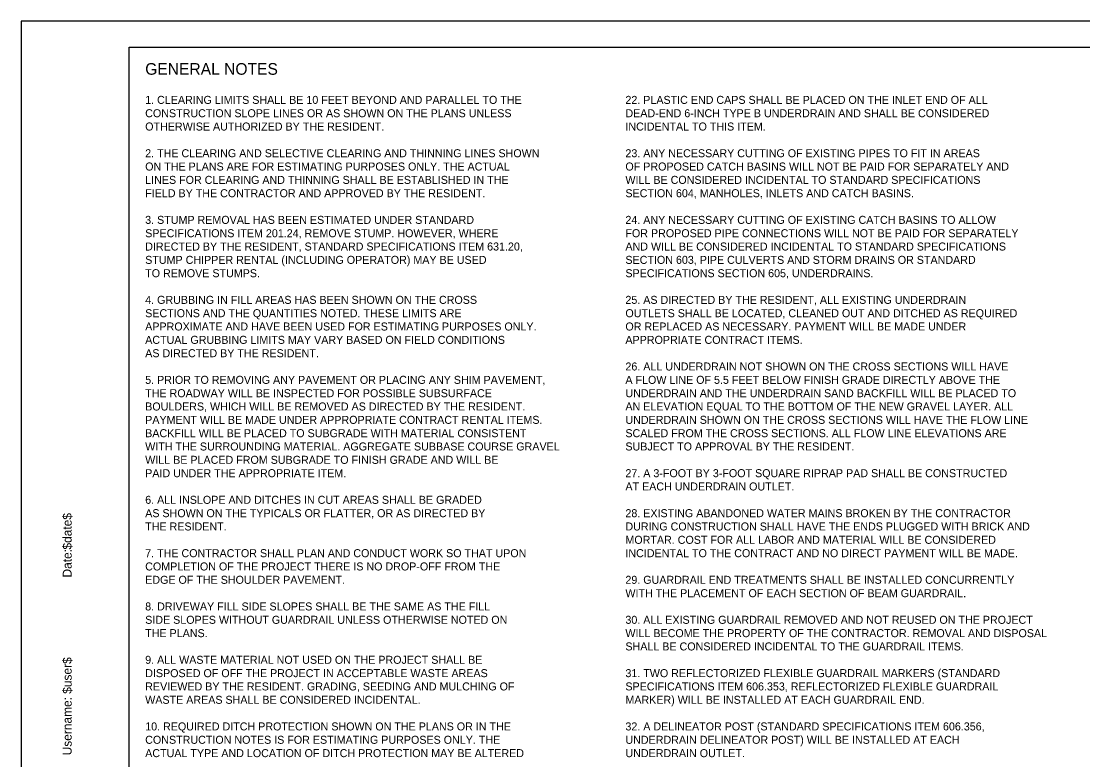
# Model space of a CAD drawing. Extents: x -0.13 to 2.72, y -0.05 to 1.78.
# Drawn here: x -0.135 to 1.191, y 0.859 to 1.782 of the extents above; entities that cross this region are included whole.
import ezdxf

# ---------------------------------------------------------------- set-up
doc = ezdxf.new("R2010")
doc.units = 0
for name, color, linetype in [('BORDER', 7, 'Continuous'), ('DIMENSIONS', 7, 'Continuous'), ('PLOT BOUNDARY', 7, 'Continuous')]:
    doc.layers.add(name, color=color, linetype=linetype)

msp = doc.modelspace()

# ---------------------------------------------------------------- linework, layer by layer
at = {"layer": 'BORDER'}
msp.add_lwpolyline([(0, 1.75), (2.6667, 1.75), (2.6667, 0), (0, 0)], close=True, dxfattribs=at)
at = {"layer": 'PLOT BOUNDARY'}
msp.add_lwpolyline([(-0.1349, -0.051), (2.6984, -0.051), (2.6984, 1.7823), (-0.1349, 1.7823)], close=True, dxfattribs=at)

# ---------------------------------------------------------------- texts
at = {"layer": 'BORDER'}
for s, p in [('$date$', (-0.0719, 1.1218)), ('Date:', (-0.0719, 1.0869)), ('$user$', (-0.0719, 0.9415)), ('Username:', (-0.0719, 0.8645))]:
    msp.add_text(s, height=0.01116, rotation=90, dxfattribs=at).set_placement(p)
at = {"layer": 'DIMENSIONS'}
for s, height, p in [('GENERAL NOTES', 0.014583, (0.02, 1.7154)), ('1. CLEARING LIMITS SHALL BE 10 FEET BEYOND AND PARALLEL TO THE ', 0.01, (0.02, 1.679)), ('22. PLASTIC END CAPS SHALL BE PLACED ON THE INLET END OF ALL ', 0.01, (0.62, 1.679)), ('CONSTRUCTION SLOPE LINES OR AS SHOWN ON THE PLANS UNLESS ', 0.01, (0.02, 1.6623)), ('DEAD-END 6-INCH TYPE B UNDERDRAIN AND SHALL BE CONSIDERED ', 0.01, (0.62, 1.6623)), ('OTHERWISE AUTHORIZED BY THE RESIDENT.  ', 0.01, (0.02, 1.6457)), ('INCIDENTAL TO THIS ITEM.', 0.01, (0.62, 1.6457)), ('2. THE CLEARING AND SELECTIVE CLEARING AND THINNING LINES SHOWN', 0.01, (0.02, 1.6123)), ('23. ANY NECESSARY CUTTING OF EXISTING PIPES TO FIT IN AREAS ', 0.01, (0.62, 1.6123)), ('ON THE PLANS ARE FOR ESTIMATING PURPOSES ONLY. THE ACTUAL ', 0.01, (0.02, 1.5957)), ('OF PROPOSED CATCH BASINS WILL NOT BE PAID FOR SEPARATELY AND ', 0.01, (0.62, 1.5957)), ('LINES FOR CLEARING AND THINNING SHALL BE ESTABLISHED IN THE ', 0.01, (0.02, 1.579)), ('WILL BE CONSIDERED INCIDENTAL TO STANDARD SPECIFICATIONS ', 0.01, (0.62, 1.579)), ('FIELD BY THE CONTRACTOR AND APPROVED BY THE RESIDENT.', 0.01, (0.02, 1.5623)), ('SECTION 604, MANHOLES, INLETS AND CATCH BASINS.', 0.01, (0.62, 1.5623)), ('3. STUMP REMOVAL HAS BEEN ESTIMATED UNDER STANDARD ', 0.01, (0.02, 1.529)), ('24. ANY NECESSARY CUTTING OF EXISTING CATCH BASINS TO ALLOW ', 0.01, (0.62, 1.529)), ('SPECIFICATIONS ITEM 201.24, REMOVE STUMP. HOWEVER, WHERE ', 0.01, (0.02, 1.5123)), ('FOR PROPOSED PIPE CONNECTIONS WILL NOT BE PAID FOR SEPARATELY ', 0.01, (0.62, 1.5123)), ('DIRECTED BY THE RESIDENT, STANDARD SPECIFICATIONS ITEM 631.20, ', 0.01, (0.02, 1.4957)), ('AND WILL BE CONSIDERED INCIDENTAL TO STANDARD SPECIFICATIONS ', 0.01, (0.62, 1.4957)), ('STUMP CHIPPER RENTAL (INCLUDING OPERATOR) MAY BE USED ', 0.01, (0.02, 1.479)), ('SECTION 603, PIPE CULVERTS AND STORM DRAINS OR STANDARD ', 0.01, (0.62, 1.479)), ('TO REMOVE STUMPS.   ', 0.01, (0.02, 1.4623)), ('SPECIFICATIONS SECTION 605, UNDERDRAINS.', 0.01, (0.62, 1.4623)), ('4. GRUBBING IN FILL AREAS HAS BEEN SHOWN ON THE CROSS ', 0.01, (0.02, 1.429)), ('25. AS DIRECTED BY THE RESIDENT, ALL EXISTING UNDERDRAIN ', 0.01, (0.62, 1.429)), ('SECTIONS AND THE QUANTITIES NOTED. THESE LIMITS ARE ', 0.01, (0.02, 1.4123)), ('OUTLETS SHALL BE LOCATED, CLEANED OUT AND DITCHED AS REQUIRED ', 0.01, (0.62, 1.4123)), ('APPROXIMATE AND HAVE BEEN USED FOR ESTIMATING PURPOSES ONLY.', 0.01, (0.02, 1.3957)), ('OR REPLACED AS NECESSARY. PAYMENT WILL BE MADE UNDER ', 0.01, (0.62, 1.3957)), ('ACTUAL GRUBBING LIMITS MAY VARY BASED ON FIELD CONDITIONS ', 0.01, (0.02, 1.379)), ('APPROPRIATE CONTRACT ITEMS.', 0.01, (0.62, 1.379)), ('AS DIRECTED BY THE RESIDENT. ', 0.01, (0.02, 1.3623)), ('26. ALL UNDERDRAIN NOT SHOWN ON THE CROSS SECTIONS WILL HAVE ', 0.01, (0.62, 1.3457)), ('5. PRIOR TO REMOVING ANY PAVEMENT OR PLACING ANY SHIM PAVEMENT, ', 0.01, (0.02, 1.329)), ('A FLOW LINE OF 5.5 FEET BELOW FINISH GRADE DIRECTLY ABOVE THE ', 0.01, (0.62, 1.329)), ('THE ROADWAY WILL BE INSPECTED FOR POSSIBLE SUBSURFACE', 0.01, (0.02, 1.3123)), ('UNDERDRAIN AND THE UNDERDRAIN SAND BACKFILL WILL BE PLACED TO ', 0.01, (0.62, 1.3123)), ('BOULDERS, WHICH WILL BE REMOVED AS DIRECTED BY THE RESIDENT. ', 0.01, (0.02, 1.2957)), ('AN ELEVATION EQUAL TO THE BOTTOM OF THE NEW GRAVEL LAYER. ALL ', 0.01, (0.62, 1.2957)), ('PAYMENT WILL BE MADE UNDER APPROPRIATE CONTRACT RENTAL ITEMS. ', 0.01, (0.02, 1.279)), ('UNDERDRAIN SHOWN ON THE CROSS SECTIONS WILL HAVE THE FLOW LINE ', 0.01, (0.62, 1.279)), ('BACKFILL WILL BE PLACED TO SUBGRADE WITH MATERIAL CONSISTENT ', 0.01, (0.02, 1.2623)), ('SCALED FROM THE CROSS SECTIONS. ALL FLOW LINE ELEVATIONS ARE ', 0.01, (0.62, 1.2623)), ('WITH THE SURROUNDING MATERIAL. AGGREGATE SUBBASE COURSE GRAVEL', 0.01, (0.02, 1.2457)), ('SUBJECT TO APPROVAL BY THE RESIDENT.  ', 0.01, (0.62, 1.2457)), ('WILL BE PLACED FROM SUBGRADE TO FINISH GRADE AND WILL BE ', 0.01, (0.02, 1.229)), ('PAID UNDER THE APPROPRIATE ITEM. ', 0.01, (0.02, 1.2123)), ('27. A 3-FOOT BY 3-FOOT SQUARE RIPRAP PAD SHALL BE CONSTRUCTED ', 0.01, (0.62, 1.2123)), ('AT EACH UNDERDRAIN OUTLET.', 0.01, (0.62, 1.1957)), ('6. ALL INSLOPE AND DITCHES IN CUT AREAS SHALL BE GRADED', 0.01, (0.02, 1.179)), ('AS SHOWN ON THE TYPICALS OR FLATTER, OR AS DIRECTED BY ', 0.01, (0.02, 1.1623)), ('28. EXISTING ABANDONED WATER MAINS BROKEN BY THE CONTRACTOR ', 0.01, (0.62, 1.1623)), ('THE RESIDENT.', 0.01, (0.02, 1.1457)), ('DURING CONSTRUCTION SHALL HAVE THE ENDS PLUGGED WITH BRICK AND ', 0.01, (0.62, 1.1457)), ('MORTAR. COST FOR ALL LABOR AND MATERIAL WILL BE CONSIDERED ', 0.01, (0.62, 1.129)), ('7. THE CONTRACTOR SHALL PLAN AND CONDUCT WORK SO THAT UPON ', 0.01, (0.02, 1.1123)), ('INCIDENTAL TO THE CONTRACT AND NO DIRECT PAYMENT WILL BE MADE.', 0.01, (0.62, 1.1123)), ('COMPLETION OF THE PROJECT THERE IS NO DROP-OFF FROM THE ', 0.01, (0.02, 1.0957)), ('EDGE OF THE SHOULDER PAVEMENT. ', 0.01, (0.02, 1.079)), ('29. GUARDRAIL END TREATMENTS SHALL BE INSTALLED CONCURRENTLY ', 0.01, (0.62, 1.079)), ('WITH THE PLACEMENT OF EACH SECTION OF BEAM GUARDRAIL.', 0.01, (0.62, 1.0623)), ('8. DRIVEWAY FILL SIDE SLOPES SHALL BE THE SAME AS THE FILL ', 0.01, (0.02, 1.0457)), ('SIDE SLOPES WITHOUT GUARDRAIL UNLESS OTHERWISE NOTED ON ', 0.01, (0.02, 1.029)), ('30. ALL EXISTING GUARDRAIL REMOVED AND NOT REUSED ON THE PROJECT ', 0.01, (0.62, 1.029)), ('THE PLANS.', 0.01, (0.02, 1.0123)), ('WILL BECOME THE PROPERTY OF THE CONTRACTOR. REMOVAL AND DISPOSAL ', 0.01, (0.62, 1.0123)), ('SHALL BE CONSIDERED INCIDENTAL TO THE GUARDRAIL ITEMS.', 0.01, (0.62, 0.9957)), ('9. ALL WASTE MATERIAL NOT USED ON THE PROJECT SHALL BE ', 0.01, (0.02, 0.979)), ('DISPOSED OF OFF THE PROJECT IN ACCEPTABLE WASTE AREAS ', 0.01, (0.02, 0.9623)), ('31. TWO REFLECTORIZED FLEXIBLE GUARDRAIL MARKERS (STANDARD ', 0.01, (0.62, 0.9623)), ('REVIEWED BY THE RESIDENT. GRADING, SEEDING AND MULCHING OF ', 0.01, (0.02, 0.9457)), ('SPECIFICATIONS ITEM 606.353, REFLECTORIZED FLEXIBLE GUARDRAIL ', 0.01, (0.62, 0.9457)), ('WASTE AREAS SHALL BE CONSIDERED INCIDENTAL.', 0.01, (0.02, 0.929)), ('MARKER) WILL BE INSTALLED AT EACH GUARDRAIL END.  ', 0.01, (0.62, 0.929)), ('10. REQUIRED DITCH PROTECTION SHOWN ON THE PLANS OR IN THE ', 0.01, (0.02, 0.8957)), ('32. A DELINEATOR POST (STANDARD SPECIFICATIONS ITEM 606.356, ', 0.01, (0.62, 0.8957)), ('CONSTRUCTION NOTES IS FOR ESTIMATING PURPOSES ONLY. THE ', 0.01, (0.02, 0.879)), ('UNDERDRAIN DELINEATOR POST) WILL BE INSTALLED AT EACH ', 0.01, (0.62, 0.879)), ('ACTUAL TYPE AND LOCATION OF DITCH PROTECTION MAY BE ALTERED ', 0.01, (0.02, 0.8623)), ('UNDERDRAIN OUTLET.', 0.01, (0.62, 0.8623))]:
    msp.add_text(s, height=height, dxfattribs=at).set_placement(p)

doc.saveas('drawing.dxf')
